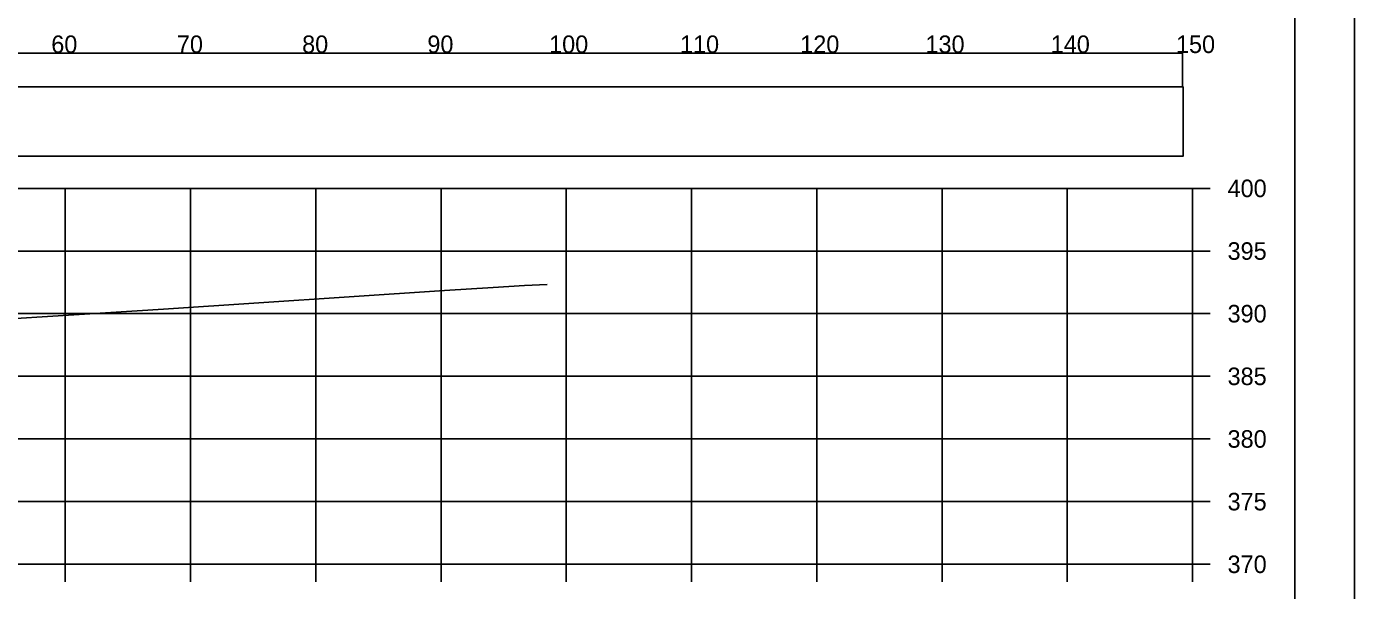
# Model space of a CAD drawing. Extents: x -37291014 to -37290680, y -936053 to -933067.
# Drawn here: x -37290786.2 to -37290680.2, y -934458 to -934413 of the extents above; entities that cross this region are included whole.
import ezdxf

# ---------------------------------------------------------------- set-up
doc = ezdxf.new("R2010")
doc.units = 0
for name, color, linetype in [('Default', 7, 'Continuous'), ('R_Axis', 7, 'Continuous'), ('R_Axis Annot', 7, 'Continuous'), ('R_Border', 7, 'Continuous'), ('R_Exist Surface', 7, 'Continuous'), ('R_Grid', 7, 'Continuous'), ('R_No Plot', 7, 'Continuous')]:
    doc.layers.add(name, color=color, linetype=linetype)

msp = doc.modelspace()

# ---------------------------------------------------------------- linework, layer by layer
at = {"layer": 'Default'}
for points in [[(-37290992.31, -934417.86), (-37290693.89, -934417.86), (-37290693.89, -934415.16), (-37290992.31, -934415.16)], [(-37290992.26, -934423.39), (-37290693.84, -934423.39), (-37290693.84, -934417.86), (-37290992.26, -934417.86)]]:
    msp.add_lwpolyline(points, close=True, dxfattribs=at)
at = {"layer": 'R_Axis'}
for p, q in [((-37290693.1, -934455.96), (-37290693.1, -934425.96)), ((-37290691.7, -934425.96), (-37290693.1, -934425.96)), ((-37290691.7, -934430.96), (-37290693.1, -934430.96)), ((-37290691.7, -934435.96), (-37290693.1, -934435.96)), ((-37290691.7, -934440.96), (-37290693.1, -934440.96)), ((-37290691.7, -934445.96), (-37290693.1, -934445.96)), ((-37290691.7, -934450.96), (-37290693.1, -934450.96)), ((-37290993.1, -934455.96), (-37290693.1, -934455.96)), ((-37290783.1, -934457.36), (-37290783.1, -934455.96)), ((-37290773.1, -934457.36), (-37290773.1, -934455.96)), ((-37290763.1, -934457.36), (-37290763.1, -934455.96)), ((-37290753.1, -934457.36), (-37290753.1, -934455.96)), ((-37290743.1, -934457.36), (-37290743.1, -934455.96)), ((-37290733.1, -934457.36), (-37290733.1, -934455.96)), ((-37290723.1, -934457.36), (-37290723.1, -934455.96)), ((-37290713.1, -934457.36), (-37290713.1, -934455.96)), ((-37290703.1, -934457.36), (-37290703.1, -934455.96)), ((-37290693.1, -934457.36), (-37290693.1, -934455.96)), ((-37290691.7, -934455.96), (-37290693.1, -934455.96))]:
    msp.add_line(p, q, dxfattribs=at)
at = {"layer": 'R_Border'}
msp.add_line((-37290684.92, -934555.96), (-37290684.92, -934350.5), dxfattribs=at)
at = {"layer": 'R_Exist Surface'}
msp.add_lwpolyline([(-37290796.33, -934436.94), (-37290775.25, -934435.6), (-37290752.83, -934434.11), (-37290748.95, -934433.86), (-37290746.44, -934433.71), (-37290744.63, -934433.63)], dxfattribs=at)
msp.add_lwpolyline([(-37290796.33, -934436.94), (-37290775.25, -934435.6), (-37290752.83, -934434.11), (-37290748.95, -934433.86), (-37290746.44, -934433.71), (-37290744.63, -934433.63)], dxfattribs=at)
at = {"layer": 'R_Grid'}
for p, q in [((-37290993.1, -934425.96), (-37290693.1, -934425.96)), ((-37290783.1, -934455.96), (-37290783.1, -934425.96)), ((-37290773.1, -934455.96), (-37290773.1, -934425.96)), ((-37290763.1, -934455.96), (-37290763.1, -934425.96)), ((-37290753.1, -934455.96), (-37290753.1, -934425.96)), ((-37290743.1, -934455.96), (-37290743.1, -934425.96)), ((-37290733.1, -934455.96), (-37290733.1, -934425.96)), ((-37290723.1, -934455.96), (-37290723.1, -934425.96)), ((-37290713.1, -934455.96), (-37290713.1, -934425.96)), ((-37290703.1, -934455.96), (-37290703.1, -934425.96)), ((-37290693.1, -934455.96), (-37290693.1, -934425.96)), ((-37290993.1, -934430.96), (-37290693.1, -934430.96)), ((-37290993.1, -934435.96), (-37290693.1, -934435.96)), ((-37290993.1, -934440.96), (-37290693.1, -934440.96)), ((-37290993.1, -934445.96), (-37290693.1, -934445.96)), ((-37290993.1, -934450.96), (-37290693.1, -934450.96)), ((-37290993.1, -934455.96), (-37290693.1, -934455.96))]:
    msp.add_line(p, q, dxfattribs=at)
at = {"layer": 'R_No Plot'}
for points in [[(-37291013.51, -934346.6), (-37290680.17, -934346.6), (-37290680.17, -934559.94), (-37291013.51, -934559.94)], [(-37290767.18, -934350.5), (-37290747.56, -934350.5), (-37290747.56, -934360.38), (-37290731.45, -934360.38), (-37290708.25, -934360.38), (-37290708.25, -934384.71), (-37290684.92, -934384.71), (-37290684.92, -934555.96), (-37291001.1, -934555.96), (-37291001.1, -934350.5)]]:
    msp.add_lwpolyline(points, close=True, dxfattribs=at)

# ---------------------------------------------------------------- texts
at = {"layer": 'R_Axis Annot'}
for s, p in [('60', (-37290784.22, -934415.16)), ('70', (-37290774.19, -934415.16)), ('80', (-37290764.19, -934415.16)), ('90', (-37290754.19, -934415.16)), ('100', (-37290744.47, -934415.16)), ('110', (-37290734.02, -934415.16)), ('120', (-37290724.42, -934415.16)), ('130', (-37290714.42, -934415.16)), ('140', (-37290704.42, -934415.16)), ('150', (-37290694.42, -934415.16)), ('400', (-37290690.3, -934426.66)), ('395', (-37290690.3, -934431.66)), ('390', (-37290690.3, -934436.66)), ('385', (-37290690.3, -934441.66)), ('380', (-37290690.3, -934446.66)), ('375', (-37290690.3, -934451.66)), ('370', (-37290690.3, -934456.66))]:
    msp.add_text(s, height=1.4, dxfattribs=at).set_placement(p)

doc.saveas('drawing.dxf')
